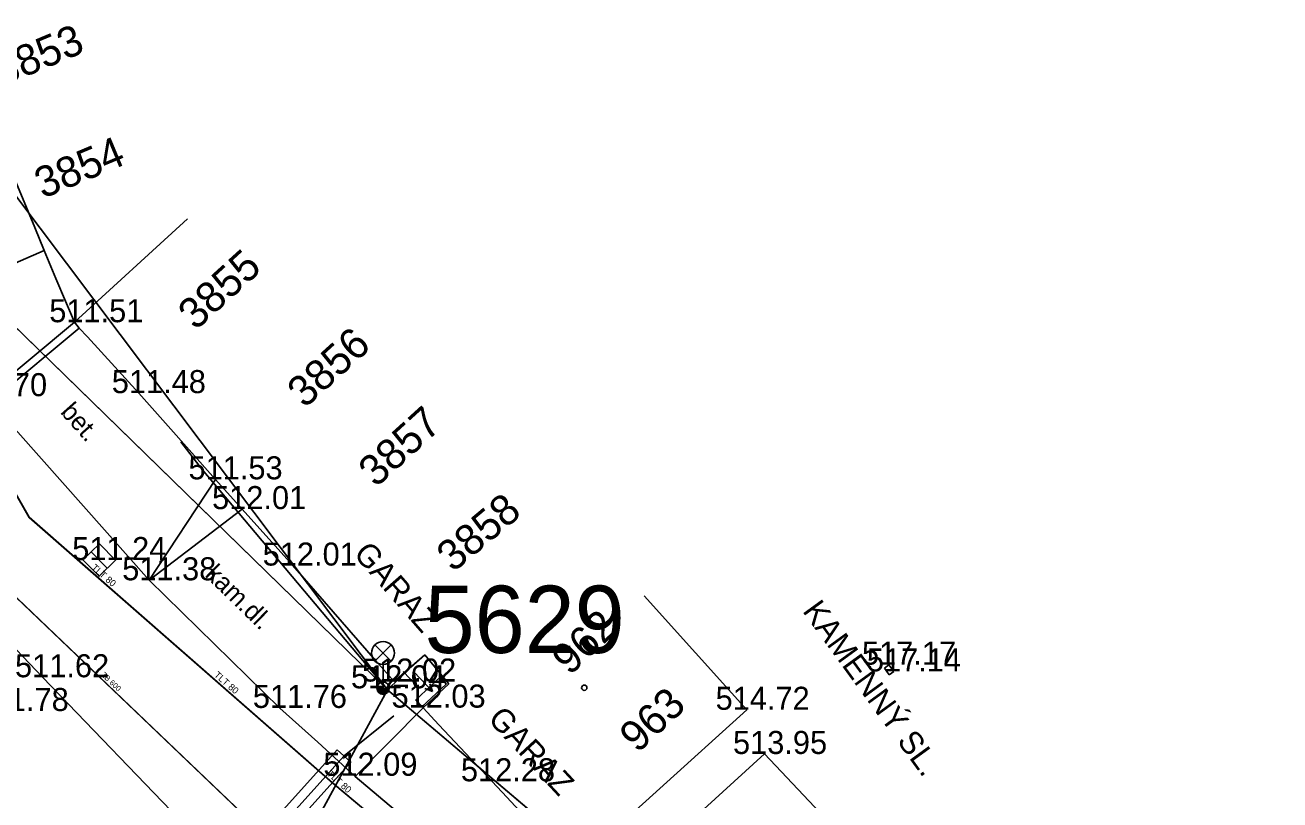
# Model space of a CAD drawing. Extents: x -669642 to -669119, y -1131006 to -1130466.
# Drawn here: x -669366.1 to -669325.2, y -1130966.24 to -1130940.99 of the extents above; entities that cross this region are included whole.
import ezdxf

# ---------------------------------------------------------------- set-up
doc = ezdxf.new("R2010")
doc.units = 0
for name, color, linetype in [('G_Bod_tecka', 7, 'Continuous'), ('G_Bod_vyska', 7, 'Continuous'), ('G_Budovy-znacky', 7, 'Continuous'), ('G_Budovy_Objekty', 7, 'Continuous'), ('G_Budovy_vstupy', 7, 'Continuous'), ('G_Cesty_Schody', 7, 'Continuous'), ('G_Cisla_jina', 7, 'Continuous'), ('G_Objekty_technicke', 7, 'Continuous'), ('G_Plochy_zpevnene', 7, 'Continuous'), ('G_Ploty_vstupy', 7, 'Continuous'), ('G_Popisy_objektu', 7, 'Continuous'), ('G_Popisy_povrchu', 7, 'Continuous'), ('G_Poznamky_odkaz', 7, 'Continuous'), ('G_Site-kanalizace', 7, 'Continuous'), ('G_Site-Rozvadece', 7, 'Continuous'), ('G_Z_CHRANICKA-TEPLOVOD_kotovane', 7, 'Continuous'), ('G_Z_ELsilove_nadz_kotovane', 7, 'Continuous'), ('G_Z_ELsilove_podz_kotovane', 7, 'Continuous'), ('G_Z_KANAL_podz_kotovane', 7, 'Continuous'), ('G_Z_VODA_podz_kotovane', 7, 'Continuous'), ('Vrstva 1', 7, 'Continuous'), ('Vrstva 13', 7, 'Continuous'), ('Vrstva 26', 7, 'Continuous'), ('Vrstva 3', 7, 'Continuous'), ('Vrstva 4', 7, 'Continuous'), ('Vrstva 5', 7, 'Continuous')]:
    doc.layers.add(name, color=color, linetype=linetype)

msp = doc.modelspace()

# ---------------------------------------------------------------- linework, layer by layer
at = {"layer": 'G_Bod_tecka'}
for p, q in [((-669364.49, -1130950.67), (-669364.49, -1130950.67)), ((-669362.39, -1130952.98), (-669362.39, -1130952.98)), ((-669359.89, -1130955.79), (-669359.89, -1130955.79)), ((-669359.02, -1130956.76), (-669359.02, -1130956.76)), ((-669363.68, -1130958.42), (-669363.68, -1130958.42)), ((-669357.37, -1130958.6), (-669357.37, -1130958.6)), ((-669362.05, -1130959.08), (-669362.05, -1130959.08)), ((-669337.94, -1130961.83), (-669337.94, -1130961.83)), ((-669365.53, -1130962.24), (-669365.53, -1130962.24)), ((-669354.07, -1130962.38), (-669354.07, -1130962.38)), ((-669337.78, -1130962.05), (-669337.78, -1130962.05)), ((-669354.43, -1130962.6), (-669354.43, -1130962.6)), ((-669357.78, -1130963.24), (-669357.78, -1130963.24)), ((-669353.12, -1130963.23), (-669353.12, -1130963.23)), ((-669342.57, -1130963.3), (-669342.57, -1130963.3)), ((-669342, -1130964.74), (-669342, -1130964.74)), ((-669355.33, -1130965.45), (-669355.33, -1130965.45)), ((-669350.87, -1130965.63), (-669350.87, -1130965.63))]:
    msp.add_line(p, q, dxfattribs=at)
at = {"layer": 'G_Budovy-znacky'}
msp.add_circle((-669347.87, -1130962.581), 0.0875, dxfattribs=at)
at = {"layer": 'G_Budovy_Objekty'}
for p, q in [((-669360.8, -1130947.3), (-669364.49, -1130950.67)), ((-669365.78, -1130947.58), (-669365.47, -1130948.33)), ((-669365.47, -1130948.33), (-669365.09, -1130949.24)), ((-669364.78, -1130949.98), (-669364.49, -1130950.67)), ((-669364.49, -1130950.67), (-669364.33, -1130950.86)), ((-669364.33, -1130950.86), (-669364.06, -1130951.15)), ((-669362.39, -1130952.98), (-669361.52, -1130953.96)), ((-669359.89, -1130955.79), (-669359.02, -1130956.76)), ((-669356.35, -1130959.77), (-669357.37, -1130958.6)), ((-669345.92, -1130959.59), (-669342.57, -1130963.3)), ((-669353.07, -1130961.51), (-669354.07, -1130962.38)), ((-669354.66, -1130961.7), (-669354.07, -1130962.38)), ((-669352.28, -1130962.45), (-669353.12, -1130963.24)), ((-669353.12, -1130963.24), (-669352.61, -1130963.79)), ((-669350.87, -1130965.64), (-669350.4, -1130966.15))]:
    msp.add_line(p, q, dxfattribs=at)
for points in [[(-669342.57, -1130963.3), (-669348.24, -1130968.43)], [(-669330.73, -1130976.67), (-669342, -1130964.74), (-669345.95, -1130968.34), (-669346.59, -1130968.93)]]:
    msp.add_lwpolyline(points, dxfattribs=at)
at = {"layer": 'G_Budovy_vstupy'}
for p, q in [((-669366.72, -1130945.31), (-669365.78, -1130947.58)), ((-669365.09, -1130949.24), (-669364.78, -1130949.98)), ((-669364.06, -1130951.15), (-669362.39, -1130952.98)), ((-669361.52, -1130953.96), (-669359.89, -1130955.79)), ((-669359.02, -1130956.76), (-669357.37, -1130958.6)), ((-669356.35, -1130959.77), (-669354.66, -1130961.7)), ((-669352.61, -1130963.79), (-669350.87, -1130965.64)), ((-669350.4, -1130966.15), (-669348.69, -1130967.98))]:
    msp.add_line(p, q, dxfattribs=at)
at = {"layer": 'G_Cesty_Schody'}
msp.add_line((-669353.12, -1130963.24), (-669355.34, -1130965.47), dxfattribs=at)
at = {"layer": 'G_Objekty_technicke'}
for points in [[(-669354.695, -1130961.185), (-669354.165, -1130961.715)], [(-669354.695, -1130961.715), (-669354.165, -1130961.185)], [(-669354.43, -1130962.6), (-669354.43, -1130961.825)]]:
    msp.add_lwpolyline(points, dxfattribs=at)
for centre, radius in [((-669354.43, -1130961.45), 0.375), ((-669354.43, -1130962.6), 0.2)]:
    msp.add_circle(centre, radius, dxfattribs=at)
for radius in [0.18, 0.16, 0.14, 0.12, 0.1, 0.08, 0.06, 0.04, 0.02]:
    msp.add_arc((-669354.43, -1130962.6), radius, 180, 0, dxfattribs=at)
at = {"layer": 'G_Plochy_zpevnene'}
for p, q in [((-669369.42, -1130950.06), (-669365.47, -1130948.33)), ((-669367.22, -1130953.26), (-669364.33, -1130950.86)), ((-669367.22, -1130953.26), (-669362.05, -1130959.08)), ((-669359.89, -1130955.79), (-669362.05, -1130959.08)), ((-669362.05, -1130959.08), (-669359.02, -1130956.76)), ((-669369.14, -1130958.46), (-669365.53, -1130962.24)), ((-669362.05, -1130959.08), (-669357.79, -1130963.25)), ((-669365.53, -1130962.24), (-669360.67, -1130967.28))]:
    msp.add_line(p, q, dxfattribs=at)
for points in [[(-669364.49, -1130950.67), (-669367.39, -1130953.08), (-669367.22, -1130953.26)], [(-669337.94, -1130961.83), (-669338.09, -1130961.94)], [(-669338.09, -1130961.94), (-669337.93, -1130962.16)], [(-669337.94, -1130961.83), (-669337.78, -1130962.05)], [(-669337.93, -1130962.16), (-669337.78, -1130962.05)], [(-669357.79, -1130963.25), (-669356.56, -1130964.36), (-669355.34, -1130965.47), (-669352.85, -1130967.57), (-669350.29, -1130969.6)]]:
    msp.add_lwpolyline(points, dxfattribs=at)
at = {"layer": 'G_Ploty_vstupy'}
for p, q in [((-669353.07, -1130961.51), (-669352.51, -1130962.18)), ((-669352.51, -1130962.18), (-669352.28, -1130962.45))]:
    msp.add_line(p, q, dxfattribs=at)
at = {"layer": 'G_Site-kanalizace'}
msp.add_line((-669363.943, -1130958.153), (-669363.416, -1130958.687), dxfattribs=at)
msp.add_lwpolyline([(-669364.209, -1130958.416), (-669363.682, -1130958.949), (-669363.149, -1130958.422), (-669363.676, -1130957.889)], close=True, dxfattribs=at)
at = {"layer": 'G_Site-Rozvadece'}
for p, q in [((-669353.771, -1130962.057), (-669353.344, -1130962.514)), ((-669353.344, -1130962.514), (-669353.417, -1130962.07)), ((-669353.417, -1130962.07), (-669352.82, -1130962.709)), ((-669353.068, -1130962.605), (-669352.82, -1130962.709)), ((-669352.82, -1130962.709), (-669352.907, -1130962.455))]:
    msp.add_line(p, q, dxfattribs=at)
msp.add_lwpolyline([(-669353.16, -1130963.2), (-669352.37, -1130962.46), (-669352.55, -1130962.22), (-669353.36, -1130962.98)], close=True, dxfattribs=at)
at = {"layer": 'G_Z_CHRANICKA-TEPLOVOD_kotovane'}
msp.add_lwpolyline([(-669355.923, -1130964.601), (-669355.476, -1130965.002), (-669358.986, -1130968.906), (-669359.433, -1130968.505)], close=True, dxfattribs=at)
at = {"layer": 'G_Z_ELsilove_nadz_kotovane'}
for points in [[(-669369.973, -1130941.817), (-669354.283, -1130962.65)], [(-669354.283, -1130962.65), (-669360.324, -1130955.467), (-669361.019, -1130954.569)], [(-669354.283, -1130962.65), (-669353.523, -1130961.907), (-669353.073, -1130961.513)], [(-669354.283, -1130962.65), (-669360.282, -1130973.697), (-669359.78, -1130973.982)]]:
    msp.add_lwpolyline(points, dxfattribs=at)
at = {"layer": 'G_Z_ELsilove_podz_kotovane'}
for points in [[(-669391.83, -1130758.66), (-669387.04, -1130787.16), (-669380.84, -1130853.82), (-669376.27, -1130911.91), (-669375.45, -1130932.67), (-669367.41, -1130949.86), (-669354.28, -1130962.65), (-669322.79, -1130989.32), (-669305.7, -1131000.09), (-669304.07, -1131000.6)], [(-669354.075, -1130963.493), (-669355.7, -1130964.802), (-669359.334, -1130968.844), (-669359.076, -1130969.487), (-669341.38, -1130984.344), (-669327.668, -1130994.92), (-669326.834, -1130996.609), (-669327.027, -1130998.311), (-669328.122, -1131000.6)]]:
    msp.add_lwpolyline(points, dxfattribs=at)
at = {"layer": 'G_Z_KANAL_podz_kotovane'}
msp.add_lwpolyline([(-669315.39, -1131000.6), (-669345.26, -1130979.82), (-669370.04, -1130956.15), (-669376.06, -1130951.12), (-669376.44, -1130950.62), (-669381.99, -1130913.61), (-669382.19, -1130912.29)], dxfattribs=at)
at = {"layer": 'G_Z_VODA_podz_kotovane'}
msp.add_lwpolyline([(-669307.945, -1131000.6), (-669314.48, -1130996.96), (-669320.35, -1130993.41), (-669321.28, -1130992.94), (-669327.74, -1130988.8), (-669333.55, -1130984.56), (-669356.07, -1130965.69), (-669365.96, -1130957.03), (-669367.51, -1130954.34), (-669368.85, -1130951.75)], dxfattribs=at)
at = {"layer": 'Vrstva 1'}
msp.add_line((-669354.28, -1130962.65), (-669354.28, -1130962.65), dxfattribs=at)
at = {"layer": 'Vrstva 13'}
msp.add_lwpolyline([(-669315.39, -1131000.6), (-669345.261, -1130979.82), (-669370.044, -1130956.15), (-669376.06, -1130951.12), (-669376.436, -1130950.621), (-669381.993, -1130913.614), (-669382.192, -1130912.286)], dxfattribs=at)
at = {"layer": 'Vrstva 26'}
msp.add_lwpolyline([(-669307.944, -1131000.6), (-669314.477, -1130996.96), (-669320.348, -1130993.408), (-669321.282, -1130992.94), (-669327.737, -1130988.804), (-669333.553, -1130984.562), (-669356.073, -1130965.685), (-669365.963, -1130957.028), (-669367.511, -1130954.339), (-669368.85, -1130951.75)], dxfattribs=at)
at = {"layer": 'Vrstva 5'}
for p, q in [((-669367.41, -1130949.86), (-669354.28, -1130962.65)), ((-669354.28, -1130962.65), (-669367.41, -1130949.86)), ((-669354.28, -1130962.65), (-669322.786, -1130989.323))]:
    msp.add_line(p, q, dxfattribs=at)

# ---------------------------------------------------------------- texts
at = {"layer": 'G_Bod_vyska'}
for s, p in [('511.51', (-669365.309, -1130950.67)), ('511.48', (-669363.271, -1130952.98)), ('510.70', (-669368.446, -1130953.08)), ('511.53', (-669360.771, -1130955.79)), ('512.01', (-669360.002, -1130956.76)), ('511.24', (-669364.561, -1130958.42)), ('512.01', (-669358.352, -1130958.6)), ('511.38', (-669362.931, -1130959.08)), ('517.17', (-669338.821, -1130961.83)), ('511.62', (-669366.424, -1130962.24)), ('512.02', (-669355.114, -1130962.38)), ('517.14', (-669338.661, -1130962.05)), ('512.04', (-669355.474, -1130962.6)), ('511.78', (-669367.741, -1130963.34)), ('511.76', (-669358.674, -1130963.24)), ('512.03', (-669354.154, -1130963.23)), ('514.72', (-669343.592, -1130963.3)), ('513.95', (-669343.024, -1130964.74)), ('512.09', (-669356.376, -1130965.45)), ('512.28', (-669351.892, -1130965.63))]:
    msp.add_text(s, height=0.75, dxfattribs=at).set_placement(p)
at = {"layer": 'G_Cisla_jina'}
for s, rotation, p in [('3853', 22.6937, (-669366.846, -1130942.993)), ('3854', 22.6937, (-669365.516, -1130946.653)), ('3855', 42.3253, (-669360.537, -1130950.959)), ('3856', 42.3253, (-669356.978, -1130953.497)), ('3857', 42.3253, (-669354.657, -1130956.079)), ('3858', 40.0224, (-669352.145, -1130958.844)), ('962', 43.0383, (-669348.347, -1130962.21)), ('963', 42.9546, (-669346.138, -1130964.739))]:
    msp.add_text(s, height=1, rotation=rotation, dxfattribs=at).set_placement(p)
at = {"layer": 'G_Popisy_objektu'}
for rotation, p in [(311.1376, (-669355.421, -1130958.237)), (312.9359, (-669351.043, -1130963.625))]:
    msp.add_text('GARAZ', height=0.75, rotation=rotation, dxfattribs=at).set_placement(p)
at = {"layer": 'G_Popisy_povrchu'}
for s, rotation, p in [('bet.', 311.5992, (-669364.97, -1130953.613)), ('kam.dl.', 315.6523, (-669360.263, -1130958.928))]:
    msp.add_text(s, height=0.6, rotation=rotation, dxfattribs=at).set_placement(p)
at = {"layer": 'G_Poznamky_odkaz'}
msp.add_text('KAMENNÝ SL.', height=0.75, rotation=306.0274, dxfattribs=at).set_placement((-669340.779, -1130960.082))
at = {"layer": 'Vrstva 3'}
msp.add_text('ZB 600', height=0.1755, rotation=316.3482, dxfattribs=at).set_placement((-669363.635, -1130962.174))
at = {"layer": 'Vrstva 4'}
for rotation, p in [(318.7982, (-669363.95, -1130958.697)), (318.8014, (-669359.953, -1130962.194)), (318.5383, (-669356.274, -1130965.415))]:
    msp.add_text('TLT 80', height=0.2194, rotation=rotation, dxfattribs=at).set_placement(p)
msp.add_text('5629', height=2.1939, dxfattribs=at).set_placement((-669353.077, -1130961.449))

doc.saveas('drawing.dxf')
